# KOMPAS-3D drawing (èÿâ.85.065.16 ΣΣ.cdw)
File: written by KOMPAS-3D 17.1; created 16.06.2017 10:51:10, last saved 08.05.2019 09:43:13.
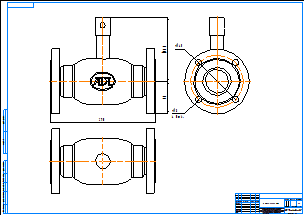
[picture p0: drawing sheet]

Sheet 1: A1, landscape

Title block, sheet 1: name: КШГ.85.065.16 фф; material: Внимание! Данный продукт является объектом авторского права ООО «Торговый Дом АДЛ». / Запрещается изменение, копирование, распространение / (в том числе путем копирования на другие сайты и ресурсы в Интернете) / или любое иное использование информации и объектов без предварительного / согласия правообладателя (ООО «Торговый Дом АДЛ»).; scale: 1:1; sheets: 1; organisation: ООО "Торговый дом АДЛ"; sheet format: A1; stored path: C:\Users\tra\Desktop\2д чертежи\Шаровые краны БИВАЛ\КШ_Бивал_серия_82_85\KOMPAS 2D\КШГ.85.065.16 фф.cdw

Views: Спереди 1, Проекционный вид 2, Проекционный вид 3
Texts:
  Klimkovich
  ADL
Dimensions and other numbers on the sheet: 290; 176,8; 90; 145; 18; 4 Отв.; 1:1; 1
